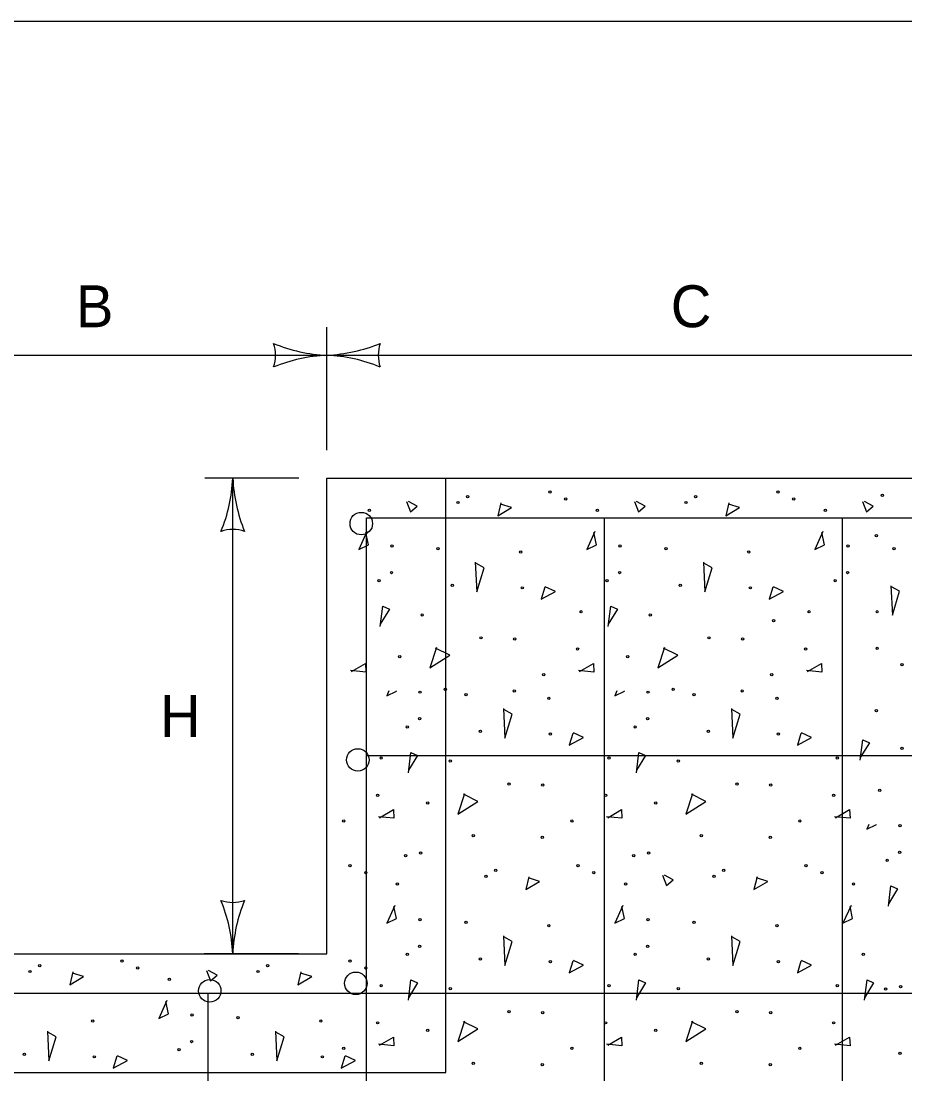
# Model space of a CAD drawing. Extents: x 49991.4 to 50021, y 49987.6 to 50011.4.
# Drawn here: x 50013.607 to 50014.87, y 49997.494 to 49998.999 of the extents above; entities that cross this region are included whole.
import ezdxf

# ---------------------------------------------------------------- set-up
doc = ezdxf.new("R2010")
doc.units = 0
for name, color, linetype in [('Level 1', 7, 'Continuous'), ('Level 2', 7, 'Continuous'), ('Level 3', 7, 'Continuous'), ('Level 4', 7, 'Continuous')]:
    doc.layers.add(name, color=color, linetype=linetype)

msp = doc.modelspace()

# ---------------------------------------------------------------- linework, layer by layer
at = {"layer": 'Level 1'}
for p, q in [((50014.0437, 49998.3456), (50015.0637, 49998.3456)), ((50014.0437, 49997.6657), (50014.0437, 49998.3456)), ((50014.1004, 49998.289), (50015.007, 49998.289)), ((50014.1004, 49997.2122), (50014.1004, 49998.289)), ((50014.4404, 49997.2122), (50014.4404, 49998.289)), ((50014.7804, 49997.2122), (50014.7804, 49998.289)), ((50014.1004, 49997.949), (50015.007, 49997.949)), ((50013.3637, 49997.6657), (50014.0437, 49997.6657)), ((50012.4004, 49997.609), (50015.007, 49997.609)), ((50013.8737, 49997.609), (50013.8737, 49997.2122))]:
    msp.add_line(p, q, dxfattribs=at)
msp.add_lwpolyline([(49999.3835, 49998.9992), (50016.7501, 49998.9992), (50016.7501, 49987.7988), (49999.3835, 49987.7988)], close=True, dxfattribs=at)
for points in [[(50014.1573, 49998.3122), (50014.163, 49998.2976), (50014.1726, 49998.3057), (50014.1601, 49998.3122)], [(50014.2923, 49998.3101), (50014.2879, 49998.2918), (50014.3076, 49998.3035), (50014.2916, 49998.3086)], [(50014.4831, 49998.3122), (50014.4889, 49998.2976), (50014.4984, 49998.3057), (50014.486, 49998.3122)], [(50014.6182, 49998.3101), (50014.6138, 49998.2918), (50014.6335, 49998.3035), (50014.6174, 49998.3086)], [(50014.8089, 49998.3122), (50014.8148, 49998.2976), (50014.8242, 49998.3057), (50014.8119, 49998.3122)], [(50014.1008, 49998.2692), (50014.0891, 49998.2437), (50014.103, 49998.2502), (50014.0993, 49998.2677)], [(50014.4266, 49998.2692), (50014.415, 49998.2437), (50014.4289, 49998.2502), (50014.4252, 49998.2677)], [(50014.7526, 49998.2692), (50014.7408, 49998.2437), (50014.7547, 49998.2502), (50014.7511, 49998.2677)], [(50014.2557, 49998.2253), (50014.258, 49998.183), (50014.2682, 49998.2174), (50014.2565, 49998.2239)], [(50014.5817, 49998.2253), (50014.5838, 49998.183), (50014.594, 49998.2174), (50014.5824, 49998.2239)], [(50014.3551, 49998.1896), (50014.35, 49998.1728), (50014.3704, 49998.1837), (50014.3558, 49998.1903)], [(50014.681, 49998.1896), (50014.6759, 49998.1728), (50014.6963, 49998.1837), (50014.6818, 49998.1903)], [(50014.8496, 49998.1918), (50014.8517, 49998.1495), (50014.8619, 49998.1839), (50014.8503, 49998.1904)], [(50014.12, 49998.1334), (50014.1236, 49998.1625), (50014.1331, 49998.1582), (50014.12, 49998.137)], [(50014.4458, 49998.1334), (50014.4494, 49998.1625), (50014.4589, 49998.1582), (50014.4458, 49998.137)], [(50014.2003, 49998.1034), (50014.1908, 49998.0742), (50014.2193, 49998.0925), (50014.1989, 49998.1027)], [(50014.5261, 49998.1034), (50014.5166, 49998.0742), (50014.5452, 49998.0925), (50014.5247, 49998.1027)], [(50014.0789, 49998.0691), (50014.0987, 49998.0808), (50014.0993, 49998.0683), (50014.0775, 49998.0705)], [(50014.4048, 49998.0691), (50014.4245, 49998.0808), (50014.4252, 49998.0683), (50014.4033, 49998.0705)], [(50014.7306, 49998.0691), (50014.7503, 49998.0808), (50014.7511, 49998.0683), (50014.7291, 49998.0705)], [(50014.1323, 49998.0413), (50014.1292, 49998.0346)], [(50014.1292, 49998.0346), (50014.1431, 49998.0411)], [(50014.1431, 49998.0411), (50014.1431, 49998.0413)], [(50014.4581, 49998.0413), (50014.4551, 49998.0346)], [(50014.4551, 49998.0346), (50014.469, 49998.0411)], [(50014.469, 49998.0411), (50014.4689, 49998.0413)], [(50014.2958, 49998.0163), (50014.2981, 49997.9739), (50014.3083, 49998.0083), (50014.2966, 49998.0148)], [(50014.6218, 49998.0163), (50014.6239, 49997.9739), (50014.6341, 49998.0083), (50014.6225, 49998.0148)], [(50014.3952, 49997.9805), (50014.3901, 49997.9637), (50014.4105, 49997.9747), (50014.3959, 49997.9813)], [(50014.7211, 49997.9805), (50014.716, 49997.9637), (50014.7364, 49997.9747), (50014.7219, 49997.9813)], [(50014.8059, 49997.9425), (50014.8096, 49997.9716), (50014.819, 49997.9673), (50014.8059, 49997.9461)], [(50014.1601, 49997.9243), (50014.1637, 49997.9535), (50014.1732, 49997.9491), (50014.1601, 49997.928)], [(50014.4859, 49997.9243), (50014.4895, 49997.9535), (50014.499, 49997.9491), (50014.4859, 49997.928)], [(50014.2404, 49997.8944), (50014.2309, 49997.8651), (50014.2594, 49997.8834), (50014.239, 49997.8937)], [(50014.5662, 49997.8944), (50014.5567, 49997.8651), (50014.5853, 49997.8834), (50014.5648, 49997.8937)], [(50014.119, 49997.86), (50014.1388, 49997.8717), (50014.1394, 49997.8593), (50014.1176, 49997.8615)], [(50014.4449, 49997.86), (50014.4646, 49997.8717), (50014.4653, 49997.8593), (50014.4434, 49997.8615)], [(50014.7707, 49997.86), (50014.7904, 49997.8717), (50014.7912, 49997.8593), (50014.7692, 49997.8615)], [(50014.8182, 49997.8504), (50014.8151, 49997.8437)], [(50014.8151, 49997.8437), (50014.829, 49997.8502)], [(50014.829, 49997.8502), (50014.8289, 49997.8504)], [(50014.5232, 49997.7779), (50014.529, 49997.7634), (50014.5385, 49997.7713), (50014.5261, 49997.7779)], [(50014.3324, 49997.7757), (50014.328, 49997.7575), (50014.3477, 49997.7691), (50014.3317, 49997.7742)], [(50014.6583, 49997.7757), (50014.6539, 49997.7575), (50014.6736, 49997.7691), (50014.6575, 49997.7742)], [(50014.846, 49997.7334), (50014.8497, 49997.7626), (50014.8591, 49997.7582), (50014.846, 49997.7371)], [(50014.1409, 49997.7348), (50014.1292, 49997.7093), (50014.1431, 49997.7159), (50014.1394, 49997.7333)], [(50014.4667, 49997.7348), (50014.4551, 49997.7093), (50014.469, 49997.7159), (50014.4653, 49997.7333)], [(50014.7927, 49997.7348), (50014.7809, 49997.7093), (50014.7948, 49997.7159), (50014.7912, 49997.7333)], [(50014.2958, 49997.691), (50014.2981, 49997.6487), (50014.3083, 49997.683), (50014.2966, 49997.6896)], [(50014.6218, 49997.691), (50014.6239, 49997.6487), (50014.6341, 49997.683), (50014.6225, 49997.6896)], [(50014.3952, 49997.6552), (50014.3901, 49997.6385), (50014.4105, 49997.6493), (50014.3959, 49997.6559)], [(50014.7211, 49997.6552), (50014.716, 49997.6385), (50014.7364, 49997.6493), (50014.7219, 49997.6559)], [(50013.6807, 49997.6395), (50013.6764, 49997.6212), (50013.696, 49997.6329), (50013.68, 49997.638)], [(50013.8714, 49997.6416), (50013.8773, 49997.627), (50013.8868, 49997.6351), (50013.8744, 49997.6416)], [(50014.0065, 49997.6395), (50014.0022, 49997.6212), (50014.0219, 49997.6329), (50014.0058, 49997.638)], [(50014.1601, 49997.599), (50014.1637, 49997.6283), (50014.1732, 49997.6238), (50014.1601, 49997.6026)], [(50014.4859, 49997.599), (50014.4895, 49997.6283), (50014.499, 49997.6238), (50014.4859, 49997.6026)], [(50014.8118, 49997.599), (50014.8155, 49997.6283), (50014.8249, 49997.6238), (50014.8118, 49997.6026)], [(50013.8151, 49997.5986), (50013.8034, 49997.5731), (50013.8173, 49997.5796), (50013.8136, 49997.5971)], [(50014.2404, 49997.5691), (50014.2309, 49997.5399), (50014.2594, 49997.5581), (50014.239, 49997.5683)], [(50014.5662, 49997.5691), (50014.5567, 49997.5399), (50014.5853, 49997.5581), (50014.5648, 49997.5683)], [(50013.6442, 49997.5547), (50013.6463, 49997.5124), (50013.6567, 49997.5468), (50013.6449, 49997.5533)], [(50013.97, 49997.5547), (50013.9723, 49997.5124), (50013.9825, 49997.5468), (50013.9708, 49997.5533)], [(50014.119, 49997.5348), (50014.1388, 49997.5464), (50014.1394, 49997.534), (50014.1176, 49997.5362)], [(50014.4449, 49997.5348), (50014.4646, 49997.5464), (50014.4653, 49997.534), (50014.4434, 49997.5362)], [(50014.7707, 49997.5348), (50014.7904, 49997.5464), (50014.7912, 49997.534), (50014.7692, 49997.5362)], [(50013.7435, 49997.519), (50013.7384, 49997.5022), (50013.7589, 49997.5131), (50013.7443, 49997.5197)], [(50014.0694, 49997.519), (50014.0642, 49997.5022), (50014.0847, 49997.5131), (50014.0701, 49997.5197)]]:
    msp.add_lwpolyline(points, dxfattribs=at)
for centre, radius in [((50014.2448, 49998.3192), 0.00165), ((50014.3624, 49998.3257), 0.00165), ((50014.5706, 49998.3192), 0.00165), ((50014.6882, 49998.3257), 0.00165), ((50014.8375, 49998.3211), 0.00165), ((50014.2309, 49998.3108), 0.00165), ((50014.385, 49998.3159), 0.00165), ((50014.5568, 49998.3108), 0.00165), ((50014.7109, 49998.3159), 0.00165), ((50014.0928, 49998.2806), 0.0161), ((50014.1044, 49998.2998), 0.00165), ((50014.4303, 49998.2998), 0.00165), ((50014.7561, 49998.2998), 0.00165), ((50014.8289, 49998.2635), 0.00165), ((50014.1367, 49998.2487), 0.00165), ((50014.2024, 49998.245), 0.00165), ((50014.4626, 49998.2487), 0.00165), ((50014.5283, 49998.245), 0.00165), ((50014.7884, 49998.2487), 0.00165), ((50014.8541, 49998.245), 0.00165), ((50014.3207, 49998.2399), 0.00165), ((50014.6466, 49998.2399), 0.00165), ((50014.1183, 49998.1991), 0.00165), ((50014.136, 49998.2107), 0.00165), ((50014.4441, 49998.1991), 0.00165), ((50014.4619, 49998.2107), 0.00165), ((50014.77, 49998.1991), 0.00165), ((50014.7877, 49998.2107), 0.00165), ((50014.2229, 49998.1925), 0.00165), ((50014.3229, 49998.1888), 0.00165), ((50014.5487, 49998.1925), 0.00165), ((50014.6488, 49998.1888), 0.00165), ((50014.4069, 49998.1545), 0.00165), ((50014.7328, 49998.1545), 0.00165), ((50014.83, 49998.1545), 0.00165), ((50014.1798, 49998.1501), 0.00165), ((50014.5057, 49998.1501), 0.00165), ((50014.682, 49998.1419), 0.00165), ((50014.2638, 49998.1173), 0.00165), ((50014.312, 49998.1158), 0.00165), ((50014.5896, 49998.1173), 0.00165), ((50014.6378, 49998.1158), 0.00165), ((50014.4018, 49998.1012), 0.00165), ((50014.7277, 49998.1012), 0.00165), ((50014.83, 49998.1021), 0.00165), ((50014.1477, 49998.0902), 0.00165), ((50014.4735, 49998.0902), 0.00165), ((50014.8656, 49998.0791), 0.00165), ((50014.3536, 49998.0647), 0.00165), ((50014.6794, 49998.0647), 0.00165), ((50014.1768, 49998.0396), 0.00165), ((50014.2127, 49998.0435), 0.00165), ((50014.2425, 49998.036), 0.00165), ((50014.3113, 49998.0413), 0.00165), ((50014.5027, 49998.0396), 0.00165), ((50014.5385, 49998.0435), 0.00165), ((50014.5684, 49998.036), 0.00165), ((50014.6371, 49998.0413), 0.00165), ((50014.3608, 49998.0309), 0.00165), ((50014.6867, 49998.0309), 0.00165), ((50014.1761, 49998.0017), 0.00165), ((50014.502, 49998.0017), 0.00165), ((50014.8289, 49998.013), 0.00165), ((50014.1584, 49997.99), 0.00165), ((50014.4842, 49997.99), 0.00165), ((50014.263, 49997.9834), 0.00165), ((50014.363, 49997.9797), 0.00165), ((50014.5888, 49997.9834), 0.00165), ((50014.6889, 49997.9797), 0.00165), ((50014.088, 49997.9427), 0.0161), ((50014.8657, 49997.9592), 0.00165), ((50014.1212, 49997.9454), 0.00165), ((50014.447, 49997.9454), 0.00165), ((50014.7729, 49997.9454), 0.00165), ((50014.2199, 49997.9411), 0.00165), ((50014.5458, 49997.9411), 0.00165), ((50014.3039, 49997.9082), 0.00165), ((50014.3521, 49997.9067), 0.00165), ((50014.6297, 49997.9082), 0.00165), ((50014.6779, 49997.9067), 0.00165), ((50014.8336, 49997.8993), 0.00165), ((50014.1161, 49997.8921), 0.00165), ((50014.1878, 49997.8812), 0.00165), ((50014.4419, 49997.8921), 0.00165), ((50014.5136, 49997.8812), 0.00165), ((50014.7678, 49997.8921), 0.00165), ((50014.0678, 49997.8556), 0.00165), ((50014.3937, 49997.8556), 0.00165), ((50014.7195, 49997.8556), 0.00165), ((50014.8627, 49997.8487), 0.00165), ((50014.2528, 49997.8344), 0.00165), ((50014.3514, 49997.8322), 0.00165), ((50014.5786, 49997.8344), 0.00165), ((50014.6772, 49997.8322), 0.00165), ((50014.1562, 49997.806), 0.00165), ((50014.1775, 49997.8096), 0.00165), ((50014.4821, 49997.806), 0.00165), ((50014.5034, 49997.8096), 0.00165), ((50014.862, 49997.8108), 0.00165), ((50014.0766, 49997.7914), 0.00165), ((50014.4025, 49997.7914), 0.00165), ((50014.7283, 49997.7914), 0.00165), ((50014.8443, 49997.7991), 0.00165), ((50014.0993, 49997.7815), 0.00165), ((50014.271, 49997.7764), 0.00165), ((50014.2849, 49997.7848), 0.00165), ((50014.4251, 49997.7815), 0.00165), ((50014.5969, 49997.7764), 0.00165), ((50014.6107, 49997.7848), 0.00165), ((50014.751, 49997.7815), 0.00165), ((50014.1445, 49997.7655), 0.00165), ((50014.4704, 49997.7655), 0.00165), ((50014.7962, 49997.7655), 0.00165), ((50014.1768, 49997.7143), 0.00165), ((50014.2425, 49997.7107), 0.00165), ((50014.3608, 49997.7056), 0.00165), ((50014.5027, 49997.7143), 0.00165), ((50014.5684, 49997.7107), 0.00165), ((50014.6867, 49997.7056), 0.00165), ((50014.1761, 49997.6764), 0.00165), ((50014.502, 49997.6764), 0.00165), ((50014.1584, 49997.6647), 0.00165), ((50014.263, 49997.6581), 0.00165), ((50014.4842, 49997.6647), 0.00165), ((50014.5888, 49997.6581), 0.00165), ((50014.8101, 49997.6647), 0.00165), ((50013.6193, 49997.6402), 0.00165), ((50013.6332, 49997.6486), 0.00165), ((50013.7508, 49997.6551), 0.00165), ((50013.7734, 49997.6453), 0.00165), ((50013.9452, 49997.6402), 0.00165), ((50013.959, 49997.6486), 0.00165), ((50014.0766, 49997.6551), 0.00165), ((50014.0993, 49997.6453), 0.00165), ((50014.363, 49997.6544), 0.00165), ((50014.6889, 49997.6544), 0.00165), ((50013.8187, 49997.6292), 0.00165), ((50013.8762, 49997.6126), 0.0161), ((50014.0851, 49997.6233), 0.0161), ((50014.1212, 49997.6201), 0.00165), ((50014.2199, 49997.6158), 0.00165), ((50014.447, 49997.6201), 0.00165), ((50014.5458, 49997.6158), 0.00165), ((50014.7729, 49997.6201), 0.00165), ((50014.8421, 49997.6151), 0.00165), ((50014.8634, 49997.6187), 0.00165), ((50014.3039, 49997.5829), 0.00165), ((50014.3521, 49997.5814), 0.00165), ((50014.6297, 49997.5829), 0.00165), ((50014.6779, 49997.5814), 0.00165), ((50013.7091, 49997.5693), 0.00165), ((50013.851, 49997.5781), 0.00165), ((50013.9167, 49997.5744), 0.00165), ((50014.035, 49997.5693), 0.00165), ((50014.1161, 49997.5668), 0.00165), ((50014.4419, 49997.5668), 0.00165), ((50014.7678, 49997.5668), 0.00165), ((50014.1878, 49997.5559), 0.00165), ((50014.5136, 49997.5559), 0.00165), ((50013.8502, 49997.5401), 0.00165), ((50013.6113, 49997.5219), 0.00165), ((50013.8325, 49997.5285), 0.00165), ((50013.9371, 49997.5219), 0.00165), ((50014.0678, 49997.5303), 0.00165), ((50014.3937, 49997.5303), 0.00165), ((50014.7195, 49997.5303), 0.00165), ((50014.8627, 49997.5234), 0.00165), ((50013.7113, 49997.5182), 0.00165), ((50014.0372, 49997.5182), 0.00165), ((50014.2528, 49997.5091), 0.00165), ((50014.3514, 49997.5069), 0.00165), ((50014.5786, 49997.5091), 0.00165), ((50014.6772, 49997.5069), 0.00165)]:
    msp.add_circle(centre, radius, dxfattribs=at)
at = {"layer": 'Level 3'}
for p, q in [((50014.0437, 49998.3856), (50014.0437, 49998.5614)), ((50012.3438, 49998.5214), (50015.0637, 49998.5214)), ((50014.0037, 49998.3456), (50013.8692, 49998.3456)), ((50013.9092, 49997.6657), (50013.9092, 49998.3456)), ((50014.0029, 49997.6657), (50013.8684, 49997.6657))]:
    msp.add_line(p, q, dxfattribs=at)
for centre, radius, start, end in [((50014.0528, 49998.7435), 0.2223, 247.456, 267.6395), ((50013.9154, 49998.5214), 0.0548, 342.1388, 17.8612), ((50014.0322, 49998.7541), 0.233, 272.8273, 292.0772), ((50014.1719, 49998.5214), 0.0548, 162.1388, 197.8612), ((50014.0552, 49998.2887), 0.233, 92.8273, 112.0772), ((50014.0345, 49998.2992), 0.2223, 67.456, 87.6395), ((50013.687, 49998.3547), 0.2223, 337.456, 357.6395), ((50014.1419, 49998.3571), 0.233, 182.8273, 202.0772), ((50013.9092, 49998.2174), 0.0548, 72.1388, 107.8612), ((50013.9092, 49997.7939), 0.0548, 252.1388, 287.8612), ((50013.6764, 49997.6542), 0.233, 2.8273, 22.0772), ((50014.1313, 49997.6565), 0.2223, 157.456, 177.6395)]:
    msp.add_arc(centre, radius, start, end, dxfattribs=at)
at = {"layer": 'Level 4'}
for p, q in [((50014.2137, 49997.4956), (50014.2137, 49998.3456)), ((50013.1937, 49997.4956), (50014.2137, 49997.4956))]:
    msp.add_line(p, q, dxfattribs=at)

# ---------------------------------------------------------------- texts
at = {"layer": 'Level 2'}
for s, p in [('B', (50013.6851, 49998.5614)), ('C', (50014.5351, 49998.5614)), ('H', (50013.8052, 49997.9756))]:
    msp.add_text(s, height=0.06, dxfattribs=at).set_placement(p)

doc.saveas('drawing.dxf')
